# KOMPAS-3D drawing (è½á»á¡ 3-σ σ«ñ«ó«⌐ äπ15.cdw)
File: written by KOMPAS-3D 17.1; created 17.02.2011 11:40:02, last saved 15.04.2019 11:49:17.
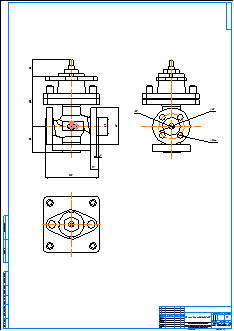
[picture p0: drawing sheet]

Title block, sheet 1: name: Клапан 3-х ходовой Ду15; material: Внимание! Данный продукт является объектом авторского права ООО «Торговый Дом АДЛ». / Запрещается изменение, копирование, распространение / (в том числе путем копирования на другие сайты и ресурсы в Интернете) / или любое иное использование информации и объектов без предварительного / согласия правообладателя (ООО «Торговый Дом АДЛ»).; scale: 1:1; sheets: 1; organisation: ООО "Торговый дом АДЛ"; sheet format: A1; stored path: \\adlc.lan\data\АДЛ_ПКД\3D-модели\ADL production\Клапаны ГРАНРЕГ\Трёхходовой клапан КМ307Ф\KOMPAS 2D\Клапан 3-х ходовой Ду15.cdw

Views: Спереди 1, Проекционный вид 2, Проекционный вид 3
Dimensions and other numbers on the sheet: 66; 126; 43; 135; 3; 19; 65; 14; 47; 95; 15; 1:1; 1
